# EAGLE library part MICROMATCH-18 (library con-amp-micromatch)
MicroMaTch 18 8-215464-8 / 1-215464-8 Drawing Number C-215464 DDEController.pdf
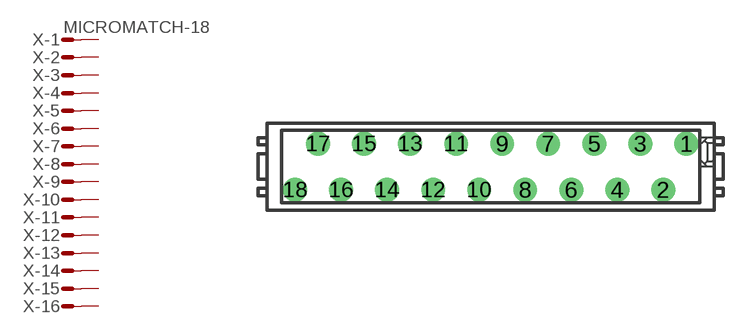
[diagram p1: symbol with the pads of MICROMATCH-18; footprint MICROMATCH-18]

Designator prefix X; gates -1=MV -2=M -3=M -4=M -5=M -6=M -7=M -8=M -9=M -10=M -11=M -12=M -13=M -14=M -15=M -16=M -17=M -18=M

## MICROMATCH-18 (MPN: 8-215464-8; OC_FARNELL: 3784691; OC_NEWARK: 19R9303)  [MICROMATCH-18]
1  -1:S  pas
2  -2:S  pas
3  -3:S  pas
4  -4:S  pas
5  -5:S  pas
6  -6:S  pas
7  -7:S  pas
8  -8:S  pas
9  -9:S  pas
10  -10:S  pas
11  -11:S  pas
12  -12:S  pas
13  -13:S  pas
14  -14:S  pas
15  -15:S  pas
16  -16:S  pas
17  -17:S  pas
18  -18:S  pas

## Footprint MICROMATCH-18 (pad centres in mm)
MicroMaTch 18 8-215464-8 / 1-215464-8 Drawing Number C-215464 DDEController.pdf
drill 0.813 round: 1 10.795,1.27; 2 9.525,-1.27; 3 8.255,1.27; 4 6.985,-1.27; 5 5.715,1.27; 6 4.445,-1.27; 7 3.175,1.27; 8 1.905,-1.27; 9 0.635,1.27; 10 -0.635,-1.27; 11 -1.905,1.27; 12 -3.175,-1.27; 13 -4.445,1.27; 14 -5.715,-1.27; 15 -6.985,1.27; 16 -8.255,-1.27; 17 -9.525,1.27; 18 -10.795,-1.27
